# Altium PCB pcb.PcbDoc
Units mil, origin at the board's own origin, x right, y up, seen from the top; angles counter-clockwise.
Board outline 2805 x 2505 mil, 2 copper layers (Top Layer, Bottom Layer); 6 components, 40 nets, 144 pads, 0 vias.
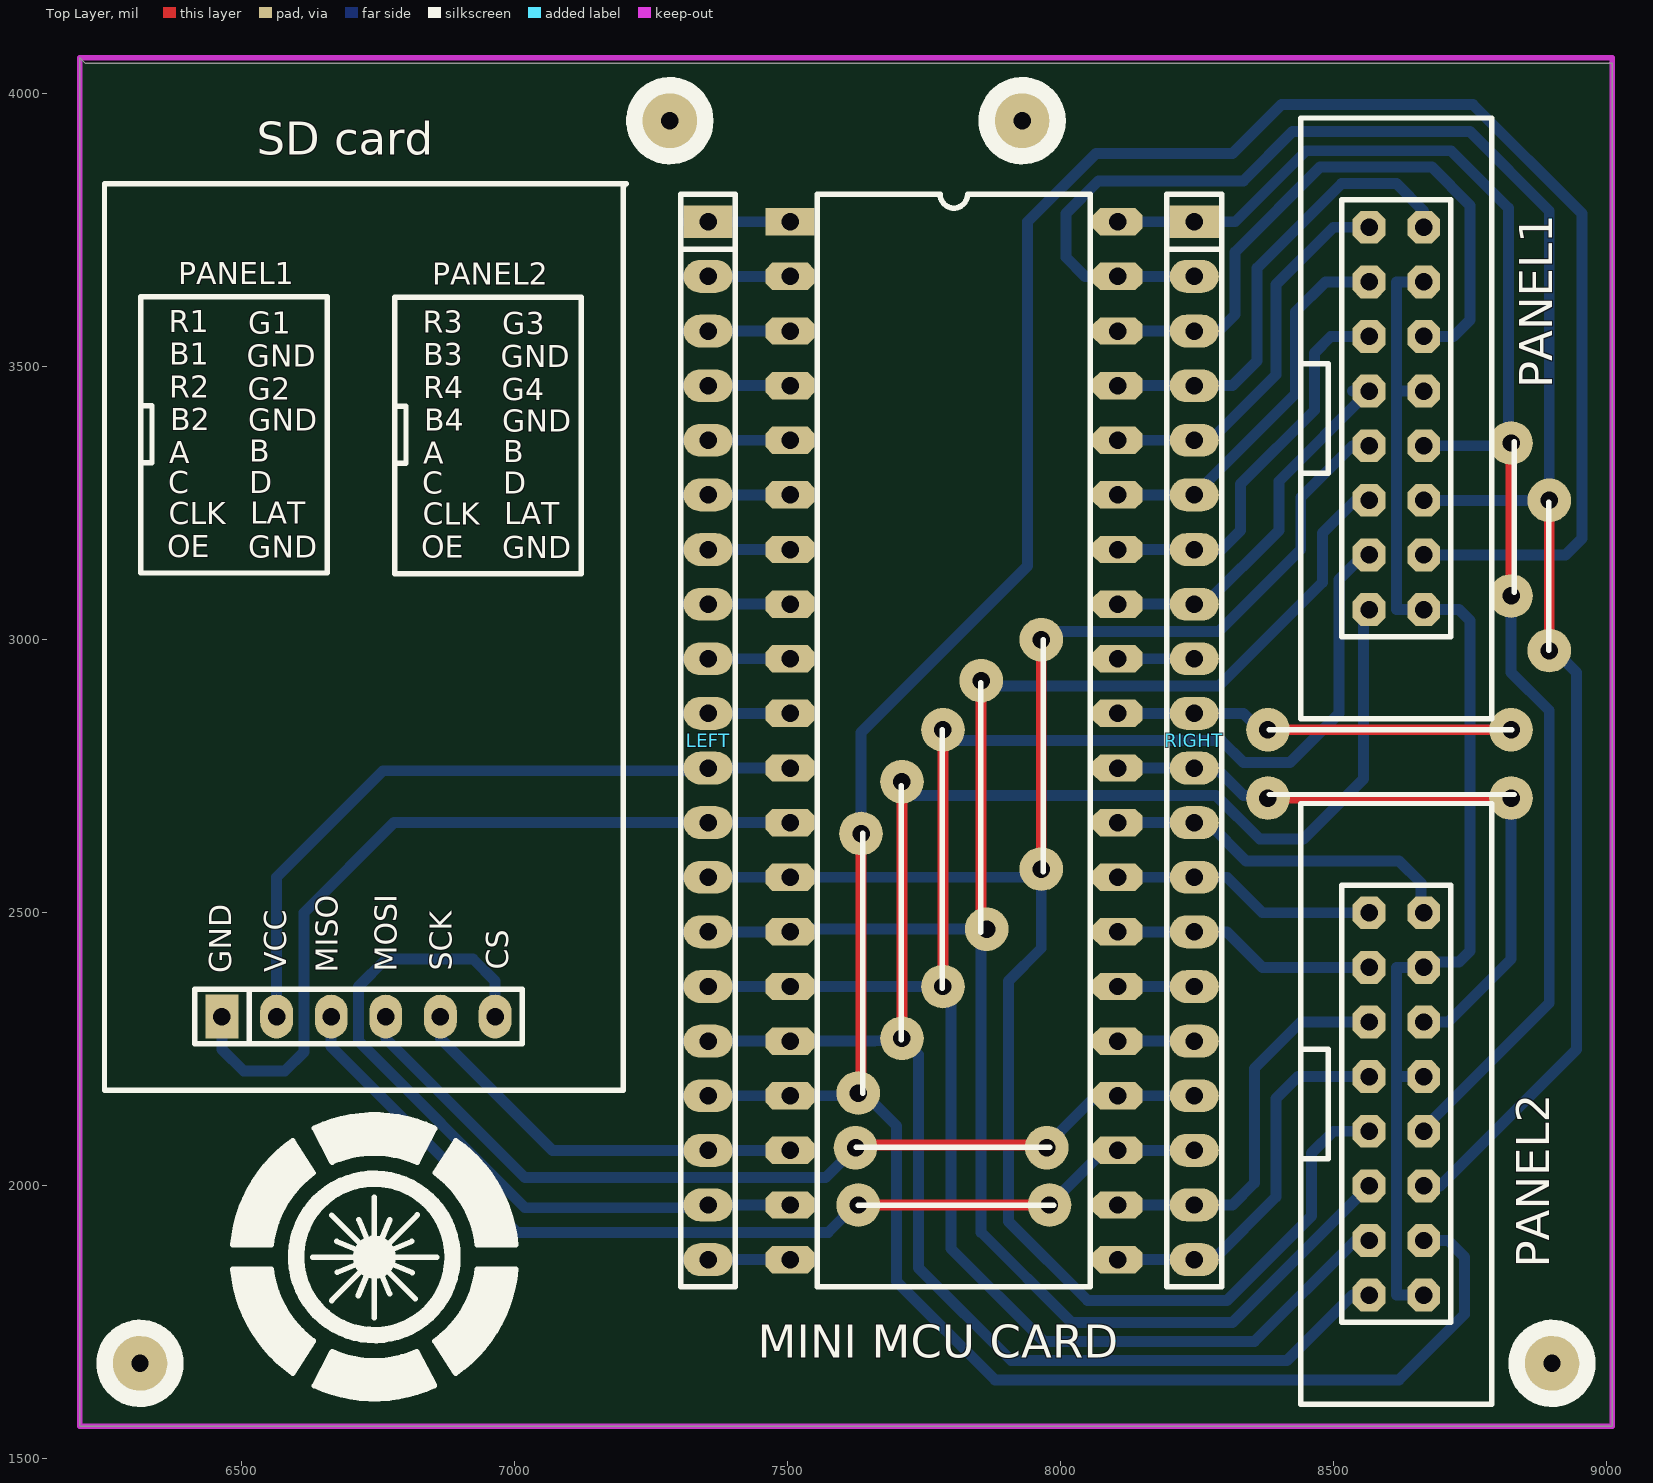
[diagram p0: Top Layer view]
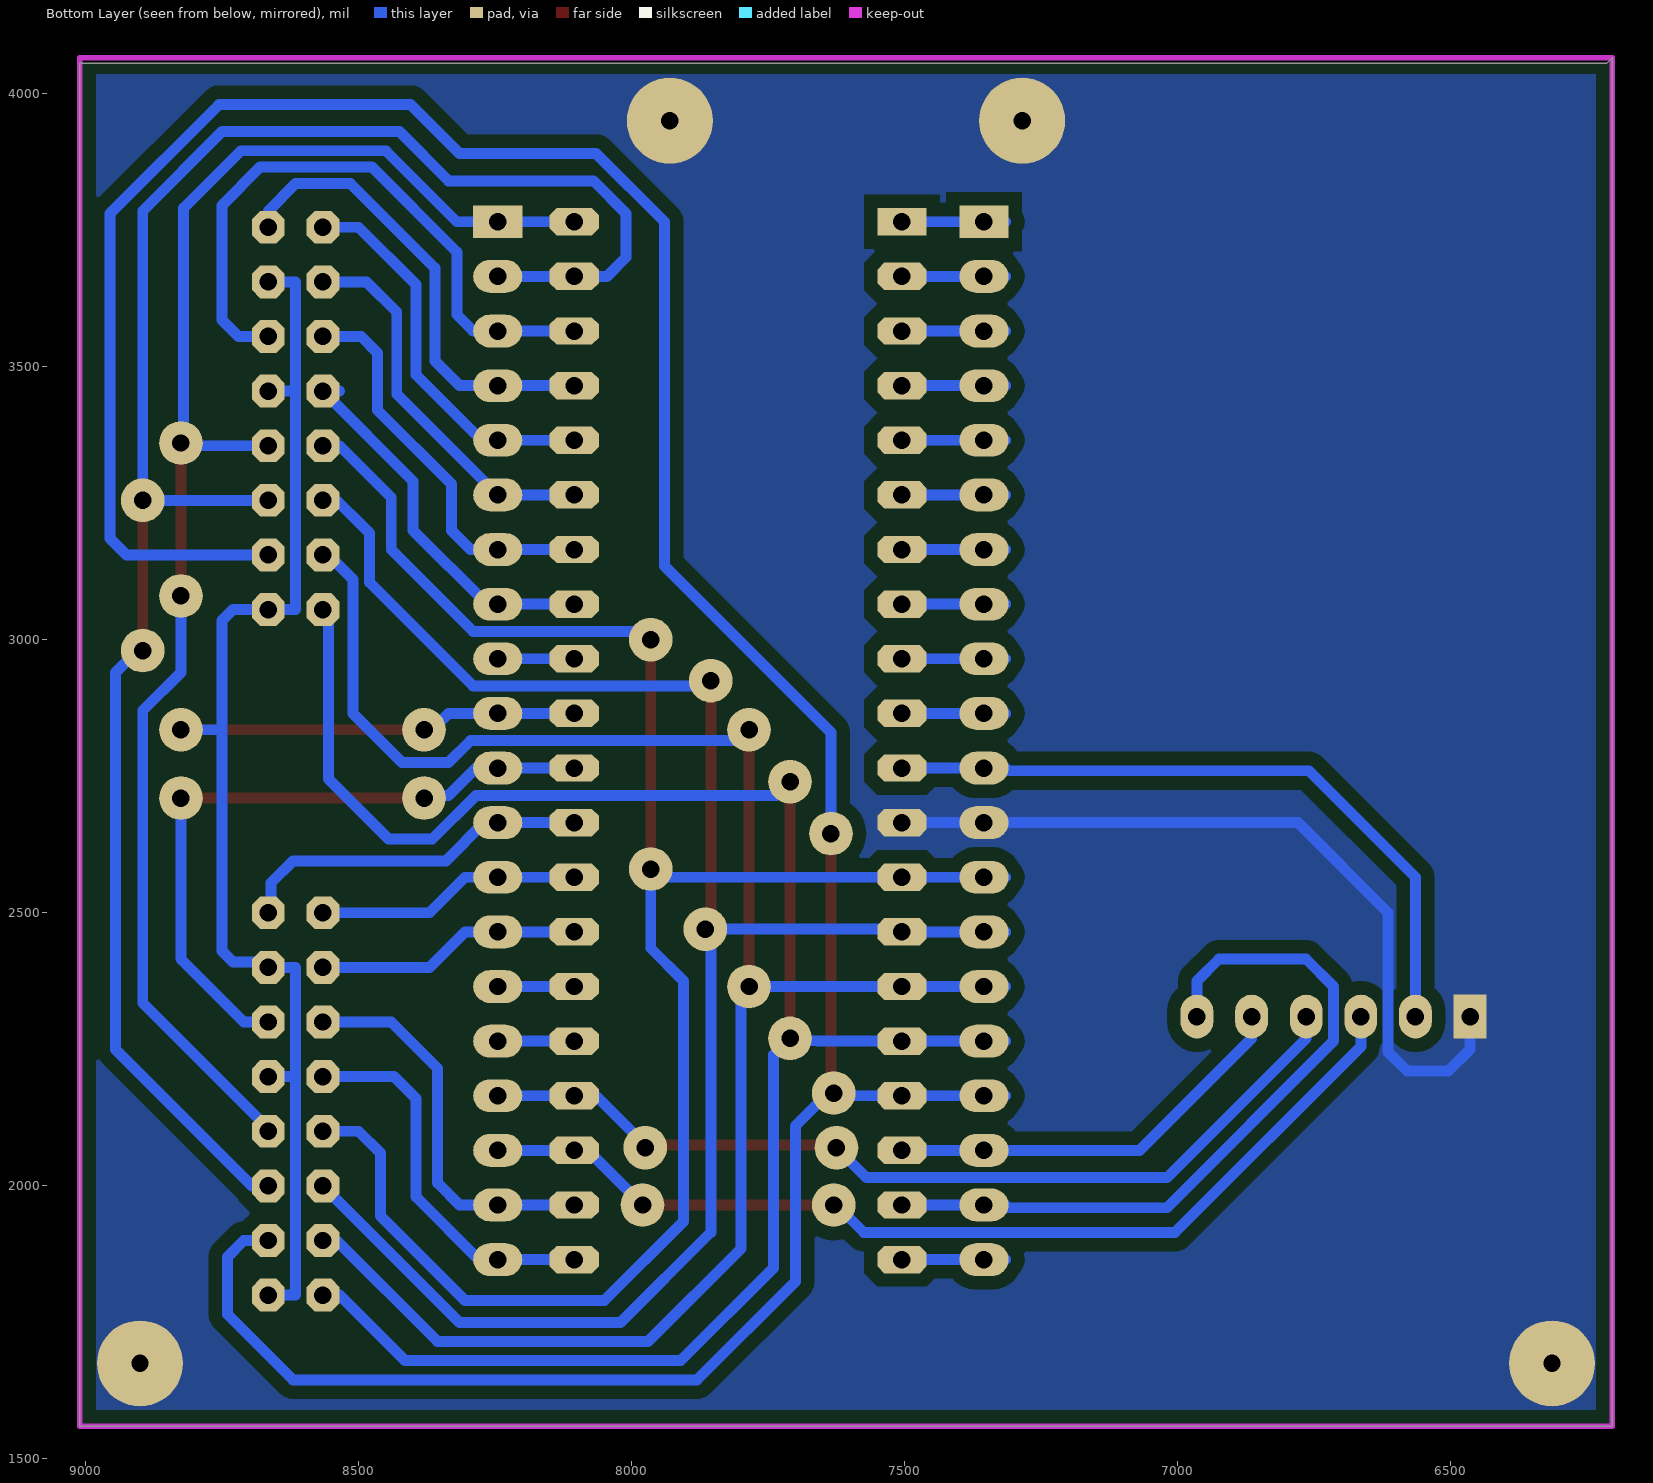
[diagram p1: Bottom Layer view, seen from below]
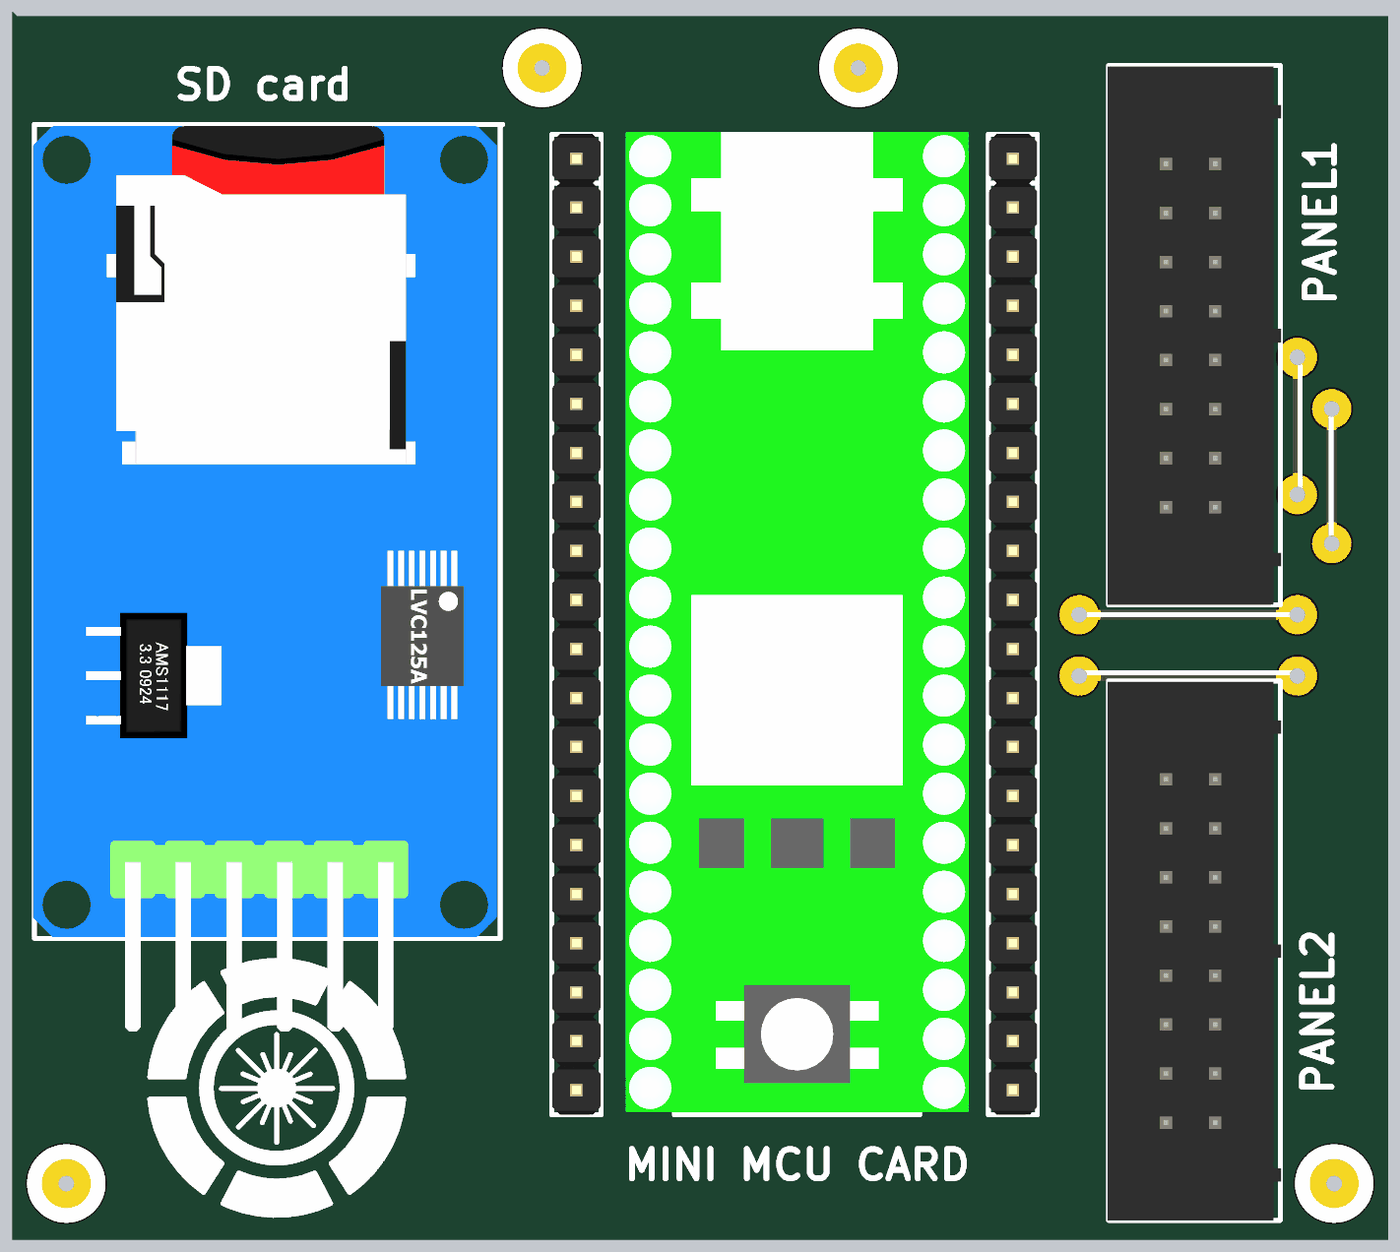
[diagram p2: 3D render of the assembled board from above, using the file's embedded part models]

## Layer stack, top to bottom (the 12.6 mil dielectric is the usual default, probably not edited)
Top Layer: signal copper 1.4
Dielectric: dielectric 12.6, FR-4, Dk 4.8
Bottom Layer: signal copper 1.4

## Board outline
6205,4065 6215,4055 9010,4055 9010,1560 6205,1560

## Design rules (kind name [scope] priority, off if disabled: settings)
Clearance [All] p1: gap=10
PolygonConnect [All] p1: connectstyle=Direct reliefconductorwidth=10 reliefentries=4 polygonreliefangle="90 Angle" airgapwidth=10
RoutingVias [All] p1: holewidth=28 width=50 viastyle="Through Hole" minholewidth=28 minwidth=50 maxholewidth=28 maxwidth=50
SolderMaskExpansion [All] p1: expansion=4
Width [All] p1: maxlimit=30 minlimit=10 preferedwidth=10 minimp=50.000000 maximp=50.000000 favimp=50.000000
28 further rules are at their usual default settings.

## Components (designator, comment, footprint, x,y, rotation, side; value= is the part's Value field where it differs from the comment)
LEFT "HDR-20" HDR-20 7355,3765 r270 top
"MINI MCU CARD" "MINI-GENERIC" "MINI - GENERIC" 7505,3765 r0 top (schematic designator PIC32)
PANEL1 "PANEL_CON" HDR-8x2 8640,3555 r270 top
PANEL2 "PANEL_CON" HDR-8x2 8640,2300 r270 top
RIGHT "HDR-20" HDR-20 8245,3765 r270 top
"SD card" "microSD" microSD 6465,2310 r0 top

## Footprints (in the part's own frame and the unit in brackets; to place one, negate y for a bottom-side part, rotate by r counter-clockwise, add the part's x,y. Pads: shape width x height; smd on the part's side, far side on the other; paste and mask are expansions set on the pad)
HDR-8x2 [mil]
  oct 60x60 hole 32: 1(-200,-75) 2(-100,-75) 3(0,-75) 4(100,-75) 5(200,-75) 6(300,-75) 7(400,-75) 8(500,-75) 9(500,25) 10(400,25) 11(300,25) 12(200,25) 13(100,25) 14(0,25) 15(-100,25) 16(-200,25)
  silkscreen extent -400,-200 700,150, body extent -398,-202 700,152, height 350
HDR-20 [mil]
  rect 60x90 hole 32: 1(0,0)
  oval 60x90 hole 32: 2(100,0) 3(200,0) 4(300,0) 5(400,0) 6(500,0) 7(600,0) 8(700,0) 9(800,0) 10(900,0) 11(1000,0) 12(1100,0) 13(1200,0) 14(1300,0) 15(1400,0) 16(1500,0) 17(1600,0) 18(1700,0) 19(1800,0) 20(1900,0)
  silkscreen extent -50,-50 1950,50, body extent -50,-49 1950,49, height 415
microSD [mil]
  rect 60x80 hole 32: 1(0,0)
  oval 60x80 hole 32: 2(100,0) 3(200,0) 4(300,0) 5(400,0) 6(500,0)
  silkscreen extent -215,-135 740,1525, body extent -217,-325 727,1521, height 636
"MINI - GENERIC" [mil]
  rect 90x50 hole 32: 1(0,0)
  oct 90x50 hole 32: 2(0,-100) 3(0,-200) 4(0,-300) 5(0,-400) 6(0,-500) 7(0,-600) 8(0,-700) 9(0,-800) 10(0,-900) 11(0,-1000) 12(0,-1100) 13(0,-1200) 14(0,-1300) 15(0,-1400) 16(0,-1500) 17(0,-1600) 18(0,-1700) 19(0,-1800) 20(0,-1900) 21(600,-1900) 22(600,-1800) 23(600,-1700) 24(600,-1600) 25(600,-1500) 26(600,-1400) 27(600,-1300) 28(600,-1200) 29(600,-1100) 30(600,-1000) 31(600,-900) 32(600,-800) 33(600,-700) 34(600,-600) 35(600,-500) 36(600,-400) 37(600,-300) 38(600,-200) 39(600,-100) 40(600,0)
  silkscreen extent 50,-1950 550,50, body extent -50,-1945 650,55, height 567

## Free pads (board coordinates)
  round 157.48 hole 32: 0(6315,1675) 0(7285,3950) 0(8900,1675) 1(7930,3950)
  round 80 hole 32: 2(7625,2070) 2(7630,1965) 2(7630,2170) 2(7635,2645) 2(7710,2270) 2(7710,2740) 2(7785,2365) 2(7785,2835) 2(7855,2925) 2(7865,2470) 2(7965,2580) 2(7965,3000) 2(7975,2070) 2(7980,1965) 2(8380,2710) 2(8380,2835) 2(8825,2710) 2(8825,2835) 2(8825,3080) 2(8825,3360) 2(8895,2980) 2(8895,3255)

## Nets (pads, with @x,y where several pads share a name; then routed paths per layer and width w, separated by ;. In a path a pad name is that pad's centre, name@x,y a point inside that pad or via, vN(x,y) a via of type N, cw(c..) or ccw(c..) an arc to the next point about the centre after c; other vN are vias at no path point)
GND: "MINI MCU CARD.31" pad.2@8380,2835 pad.2@8825,2835 PANEL1.9 PANEL1.13 PANEL1.15 PANEL2.9 PANEL2.13 PANEL2.15 RIGHT.10 | length 3094.8
  Top Layer w20: pad.2@8385,2835 8380,2835 pad.2@8825,2835
  Bottom Layer w20: 8105,2865 RIGHT.10 8335,2865 pad.2@8375,2825 ; 8615,2200 PANEL2.13@8660,2200 ; 8617.5,3455 PANEL1.13 ; PANEL2.9@8660,1800 8615,1800 8615,2400 8660,2400 8670,2410 8730,2410 8750,2430 8750,2835 ; PANEL1.15 8615,3655 8615,3055 PANEL1.9 8730,3055 8750,3035 8750,2835 ; pad.2@8825,2835 8750,2835
GND1: "MINI MCU CARD.12" "SD card.1" LEFT.12 pad.0 pad.1 | length 1454.4
  Bottom Layer w20: 6465,2310 6465,2250 6505,2210 6580,2210 6615,2245 6615,2500 6780,2665 LEFT.12 7505,2665
NetLEFT_1: "MINI MCU CARD.1" LEFT.1 | length 190
  Bottom Layer w20: LEFT.1@7315,3765 7505,3765
NetLEFT_2: "MINI MCU CARD.2" LEFT.2 | length 190
  Bottom Layer w20: LEFT.2@7315,3665 7505,3665
NetLEFT_3: "MINI MCU CARD.3" LEFT.3 | length 190
  Bottom Layer w20: LEFT.3@7315,3565 7505,3565
NetLEFT_4: "MINI MCU CARD.4" LEFT.4 | length 190
  Bottom Layer w20: LEFT.4@7315,3465 7505,3465
NetLEFT_5: "MINI MCU CARD.5" LEFT.5 | length 190
  Bottom Layer w20: LEFT.5@7315,3365 7505,3365
NetLEFT_6: "MINI MCU CARD.6" LEFT.6 | length 190
  Bottom Layer w20: LEFT.6@7315,3265 7505,3265
NetLEFT_7: "MINI MCU CARD.7" LEFT.7 | length 190
  Bottom Layer w20: LEFT.7@7315,3165 7505,3165
NetLEFT_8: "MINI MCU CARD.8" LEFT.8 | length 190
  Bottom Layer w20: LEFT.8@7315,3065 7505,3065
NetLEFT_9: "MINI MCU CARD.9" LEFT.9 | length 190
  Bottom Layer w20: LEFT.9@7315,2965 7505,2965
NetLEFT_10: "MINI MCU CARD.10" LEFT.10 | length 190
  Bottom Layer w20: LEFT.10@7315,2865 7505,2865
NetLEFT_13: "MINI MCU CARD.13" LEFT.13 pad.2@7965,2580 pad.2@7965,3000 PANEL1.5 PANEL2.5 | length 3458.4
  Top Layer w20: pad.2@7965,2580 pad.2@7965,3000
  Bottom Layer w20: LEFT.13@7315,2565 7505,2565 pad.2@7965,2565 ; pad.2@7965,2580 pad.2@7965,2565 ; pad.2@7965,3000 7980,3015 8290,3015 8440,3165 8440,3260 8535,3355 PANEL1.5 ; PANEL2.5 8500,2100 8460,2060 8460,1945 8305,1790 8050,1790 7905,1935 7905,2375 7965,2435 pad.2@7965,2565
NetLEFT_14: "MINI MCU CARD.14" LEFT.14 pad.2@7855,2925 pad.2@7865,2470 PANEL1.6 PANEL2.6 | length 3373.8
  Top Layer w20: pad.2@7855,2925 7855,2480 pad.2@7865,2470
  Bottom Layer w20: LEFT.14@7315,2465 7505,2465 ; 7510,2470 7865,2470 7855,2460 7855,1915 8020,1750 8315,1750 PANEL2.6 ; pad.2@7855,2925 7875,2915 8290,2915 8480,3105 8480,3195 PANEL1.6@8552.5,3267.5 ; PANEL1.6@8545,3255 PANEL1.6 ; PANEL2.6@8550,2000 PANEL2.6@8560,2000
NetLEFT_15: "MINI MCU CARD.15" LEFT.15 pad.2@7785,2365 pad.2@7785,2835 PANEL1.7 PANEL2.7 | length 3439
  Top Layer w20: pad.2@7785,2365 pad.2@7785,2835
  Bottom Layer w20: LEFT.15@7315,2365 7505,2365 7785,2365 7800,2350 7800,1885 7970,1715 8355,1715 8540,1900 PANEL2.7@8560,1900 ; pad.2@7785,2835 7805,2815 8295,2815 8335,2775 8420,2775 8510,2865 8510,3110 8555,3155 PANEL1.7
NetLEFT_16: "MINI MCU CARD.16" LEFT.16 pad.2@7710,2270 pad.2@7710,2740 PANEL1.8 PANEL2.8 | length 3450.6
  Top Layer w20: pad.2@7710,2270 pad.2@7710,2740
  Bottom Layer w20: LEFT.16@7315,2265 7505,2265 7660,2265 7710,2270 7740,2240 7740,1850 7910,1680 8415,1680 8535,1800 PANEL2.8@8560,1800 ; pad.2@7735,2715 8285,2715 8365,2635 8445,2635 8555,2745 8555,3045 PANEL1.8
NetLEFT_17: "MINI MCU CARD.17" LEFT.17 pad.2@7630,2170 pad.2@7635,2645 PANEL1.10 PANEL2.10 | length 5861.3
  Top Layer w20: pad.2@7635,2175 pad.2@7635,2645
  Bottom Layer w20: LEFT.17@7315,2165 7505,2165 7625,2165 pad.2@7630,2170 ; pad.2@7630,2175 7635,2175 7700,2110 7700,1825 7880,1645 8620,1645 8740,1765 8740,1870 8710,1900 PANEL2.10@8660,1900 ; pad.2@7635,2645 7635,2830 7940,3135 7940,3765 8065,3890 8315,3890 8405,3980 8755,3980 8955,3780 8955,3185 8925,3155 PANEL1.10
NetLEFT_18: "MINI MCU CARD.18" "SD card.5" LEFT.18 | length 804.9
  Bottom Layer w20: 6865,2310 6865,2270 7070,2065 LEFT.18 ; LEFT.18@7315,2065 7505,2065
NetLEFT_19: "MINI MCU CARD.19" "SD card.6" LEFT.19 | length 1403.6
  Bottom Layer w20: 6965,2310 6965,2375 6925,2415 6765,2415 6715,2365 6715,2265 7020,1960 LEFT.19@7350,1960 ; LEFT.19@7315,1965 7505,1965
NetLEFT_20: "MINI MCU CARD.20" LEFT.20 | length 190
  Bottom Layer w20: LEFT.20@7315,1865 7505,1865
"NetMINI MCU CARD_21": "MINI MCU CARD.21" PANEL2.4 RIGHT.20 | length 699.2
  Bottom Layer w20: 8105,1865 RIGHT.20 8280,1865 8395,1980 8395,2160 8435,2200 PANEL2.4@8560,2200
"NetMINI MCU CARD_22": "MINI MCU CARD.22" PANEL2.3 RIGHT.19 | length 721.8
  Bottom Layer w20: 8105,1965 RIGHT.19 8315,1965 8355,2005 8355,2215 8440,2300 PANEL2.3
"NetMINI MCU CARD_23": "MINI MCU CARD.23" "SD card.3" pad.2@7630,1965 pad.2@7980,1965 RIGHT.18 | length 1833
  Top Layer w20: pad.2@7625,1965 pad.2@7975,1965
  Bottom Layer w20: 6665,2310 6665,2255 7005,1915 7575,1915 pad.2@7625,1965 ; pad.2@7980,1965 8080,2065 8105,2065 RIGHT.18
"NetMINI MCU CARD_24": "MINI MCU CARD.24" "SD card.4" pad.2@7625,2070 pad.2@7975,2070 RIGHT.17 | length 1697.8
  Top Layer w20: pad.2@7625,2070 7630,2075 pad.2@7970,2075
  Bottom Layer w20: 6765,2310 6765,2270 7020,2015 7570,2015 7625,2070 pad.2@7610,2070 ; pad.2@7975,2075 8065,2165 8105,2165 RIGHT.17
"NetMINI MCU CARD_25": "MINI MCU CARD.25" RIGHT.16 | length 140
  Bottom Layer w20: 8105,2265 RIGHT.16
"NetMINI MCU CARD_26": "MINI MCU CARD.26" RIGHT.15 | length 140
  Bottom Layer w20: 8105,2365 RIGHT.15
"NetMINI MCU CARD_27": "MINI MCU CARD.27" PANEL2.2 RIGHT.14 | length 441.9
  Bottom Layer w20: 8105,2465 RIGHT.14 ; RIGHT.14@8285,2465 8305,2465 8370,2400 PANEL2.2@8560,2400
"NetMINI MCU CARD_28": "MINI MCU CARD.28" PANEL2.1 RIGHT.13 | length 446.9
  Bottom Layer w20: 8105,2565 RIGHT.13 ; RIGHT.13@8280,2565 8305,2565 8370,2500 PANEL2.1@8560,2500
"NetMINI MCU CARD_29": "MINI MCU CARD.29" PANEL2.16 RIGHT.12 | length 655.6
  Bottom Layer w20: 8105,2665 RIGHT.12 8270,2665 8340,2595 8620,2595 8660,2555 PANEL2.16@8660,2500
"NetMINI MCU CARD_30": "MINI MCU CARD.30" pad.2@8380,2710 pad.2@8825,2710 PANEL2.14 RIGHT.11 | length 1217.5
  Top Layer w20: pad.2@8380,2710 pad.2@8825,2710
  Bottom Layer w20: 8105,2765 RIGHT.11 ; RIGHT.11@8285,2765 8335,2715 pad.2@8390,2715 ; PANEL2.14@8660,2300 8710,2300 8825,2415 8825,2695 pad.2@8815,2705
"NetMINI MCU CARD_33": "MINI MCU CARD.33" PANEL1.4 RIGHT.8 | length 704.3
  Bottom Layer w20: 8105,3065 RIGHT.8 8265,3065 8400,3200 8400,3290 PANEL1.4 PANEL1.4@8535,3455
"NetMINI MCU CARD_34": "MINI MCU CARD.34" PANEL1.3 RIGHT.7 | length 747.8
  Bottom Layer w20: 8105,3165 RIGHT.7 8295,3165 8330,3200 8330,3285 8465,3420 8465,3525 8495,3555 PANEL1.3 PANEL1.3@8550,3555
"NetMINI MCU CARD_35": "MINI MCU CARD.35" PANEL1.2 RIGHT.6 | length 739.4
  Bottom Layer w20: 8105,3265 RIGHT.6 8430,3450 8430,3600 8485,3655 PANEL1.2 PANEL1.2@8535,3655
"NetMINI MCU CARD_36": "MINI MCU CARD.36" PANEL1.1 RIGHT.5 | length 718.2
  Bottom Layer w20: 8105,3365 RIGHT.5 8275,3365 8395,3485 8395,3650 8500,3755 PANEL1.1
"NetMINI MCU CARD_37": "MINI MCU CARD.37" PANEL1.16 RIGHT.4 | length 863.6
  Bottom Layer w20: 8105,3465 RIGHT.4 8315,3465 8360,3510 8360,3680 8515,3835 8615,3835 8665,3785 PANEL1.16
"NetMINI MCU CARD_38": "MINI MCU CARD.38" PANEL1.14 RIGHT.3 | length 1173.1
  Bottom Layer w20: 8105,3565 RIGHT.3 8290,3565 8320,3595 8320,3710 8475,3865 8680,3865 8750,3795 8750,3585 8720,3555 PANEL1.14
"NetMINI MCU CARD_39": "MINI MCU CARD.39" pad.2@8895,2980 pad.2@8895,3255 PANEL1.11 PANEL2.11 RIGHT.2 | length 3516.8
  Top Layer w20: pad.2@8895,2980 pad.2@8895,3255
  Bottom Layer w20: RIGHT.2 8105,3665 8045,3665 8010,3700 8010,3780 8070,3840 8335,3840 8425,3930 8750,3930 8895,3785 8895,3255 PANEL1.11 ; PANEL2.11@8660,2000 8695,2000 8945,2250 8945,2940 8905,2980 pad.2@8895,2980
"NetMINI MCU CARD_40": "MINI MCU CARD.40" pad.2@8825,3080 pad.2@8825,3360 PANEL1.12 PANEL2.12 RIGHT.1 | length 2788.7
  Top Layer w20: pad.2@8825,3080 pad.2@8825,3360
  Bottom Layer w20: 8105,3765 RIGHT.1 8320,3765 8450,3895 8715,3895 8820,3790 8820,3355 PANEL1.12 ; PANEL2.12@8660,2100 8895,2335 8895,2870 8825,2940 pad.2@8825,3080
VCC: "MINI MCU CARD.32" RIGHT.9 | length 140
  Bottom Layer w20: 8105,2965 RIGHT.9
VCC1: "MINI MCU CARD.11" "SD card.2" LEFT.11 | length 1335.8
  Bottom Layer w20: 6565,2295 6565,2565 6760,2760 LEFT.11@7360,2760 ; LEFT.11@7315,2765 7505,2765

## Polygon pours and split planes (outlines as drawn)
GND1 on Bottom Layer "GND1" (solid, remove dead copper, pour order 4): 6205,4055 9010,4055 9005,4050 9005,1570 9005,1565 9010,1560 6205,1560
GND1 on Bottom Layer "GND1" (solid, remove dead copper, pour order 2): 6205,4065 9010,4065 9010,1560 6205,1560

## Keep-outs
Keep-Out Layer:
  lines w10: 6205,1560 9010,1560 9010,4065 6205,4065 6205,1560

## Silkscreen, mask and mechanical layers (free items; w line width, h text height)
Top Overlay:
  circle w30: c6315,1675 r65
  circle w30: c8900,1675 r65
  circle w30: c7930,3950 r65
  circle w30: c7285,3950 r65
  circle w10: c6744,1869.5 r34.56
  circle w20: c6744,1869.5 r23.01
  circle w30: c6744,1870 r143.21
  region: 6594.87,1657.02 6609,1676 6632.59,1716.09 6589,1759.68 6564,1804 6551.66,1847.34 6484.99,1847.34 6493,1805 6507,1764 6532,1722 6561,1682 6561,1681
  region: 6821.51,1696.54 6840.53,1660 6853.88,1634.36 6805,1616 6747,1610 6687,1618 6634.54,1634.36 6654,1671 6666.39,1695.76 6702,1685 6741,1680 6781,1684
  region: 6932.7,1847.34 7003.01,1847.34 6997,1805 6987,1771 6970,1733.89 6933,1692 6893.13,1657.02 6867,1696.98 6855.01,1719.01 6884,1744 6911,1775
  region: 6855.87,2023.98 6865.44,2039 6893.11,2082.44 6950,2032 6985,1969 6998,1930 7002,1892.34 6932.7,1892.34 6924,1929 6894,1987
  region: 6666.49,2043.46 6653,2073 6634.12,2105.64 6687,2123 6757.87,2132.61 6853.88,2110.04 6841,2076 6822.29,2043.12 6806,2050 6751,2059 6691,2055
  region: 6484.99,1892.34 6484.99,1910.99 6514,1996 6559,2054 6594.87,2082.02 6606,2060 6632.11,2023.56 6594,1984 6566,1937 6553,1892.34
  lines w10: 6317,3324 6337,3324 6337,3428 6324,3428 ; 6484.99,1892.34 6555.27,1892.34 ; 6484.99,1892.66 cw(c6744,1870) 6594.87,2082.98 ; 6551.66,1847.34 6484.99,1847.34 ccw(c6744,1870) 6594.87,1657.02 6632.11,1715.44 ; 6555.31,1847.77 ccw(c6744,1870) 6632.59,1716.09 ; 6555.32,1892.33 cw(c6744,1870) 6632.14,2023.58 ; 6594.87,2082.02 6632.11,2023.56 ; 6631,1869 6858,1869 ; 6634.12,1634.36 ccw(c6744,1870) 6853.88,1634.36 6821.51,1696.54 cw(c6744,1870) 6666.69,1696.44 ; 6634.3,1634.12 6666.39,1695.76 ; 6665.59,1946.59 6819.09,1793.09 ; 6665.91,1790.09 6822.91,1947.09 ; 6666.49,2043.46 6634.12,2105.64 cw(c6744,1870) 6853.88,2105.64 ; 6666.57,2043.51 cw(c6744,1870) 6822.29,2043.12 6854.39,2104.76 ; 6675.16,1898.38 6813.1,1841.24 ; 6675.76,1841.59 6812.49,1898.23 ; 6714.62,1799.16 6772.26,1938.31 ; 6715.74,1938.31 6772.11,1802.22 ; 6744,1759 6744,1979 ; 6782,3323 6802,3323 6802,3427 6789,3427 ; 6855.68,2023.71 cw(c6744,1870) 6932.7,1892.19 ; 6855.87,2023.98 6893.11,2082.44 ; 6892.11,1657.56 6855.01,1715.8 ccw(c6744,1870) 6932.64,1847.35 ; 6893.13,1657.02 ccw(c6744,1870) 7003.01,1847.34 6932.7,1847.34 ; 6893.13,2082.98 cw(c6744,1870) 7003.01,1892.66 ; 6932.7,1892.34 7003.01,1892.34 ; 7625.98,2070.87 7980.31,2070.87 ; 7629.92,1964.57 7988.19,1964.57 ; 7637.8,2169.29 7637.8,2645.67 ; 7708.66,2267.72 7708.66,2732.28 ; 7783.46,2362.2 7783.46,2834.65 ; 7854.33,2464.57 7854.33,2921.26 ; 7968.5,2574.8 7968.5,3000 ; 8381.89,2716.54 8830.71,2716.54 ; 8381.89,2834.65 8826.77,2834.65 ; 8830.71,3086.61 8830.71,3362.2 ; 8893.7,2980.32 8893.7,3251.97 ; 6316,3122 6658,3122 6658,3628 6316,3628 6316,3122 ; 6781,3121 6781,3627 7123,3627 7123,3121 6781,3121
  text "PANEL1" at 6385,3651 h40
  text "PANEL2" at 6850,3650 h40
  text "R1" at 6368,3563 h40
  text "R3" at 6833,3562 h40
  text "G1" at 6513,3560 h40
  text "G3" at 6978,3559 h40
  text "B1" at 6369,3503 h40
  text "B3" at 6834,3502 h40
  text "GND" at 6510,3500 h40
  text "GND" at 6975,3499 h40
  text "R2" at 6369,3443 h40
  text "R4" at 6834,3442 h40
  text "G2" at 6512,3439 h40
  text "G4" at 6977,3438 h40
  text "B2" at 6370,3383 h40
  text "GND" at 6513,3382 h40
  text "B4" at 6835,3382 h40
  text "GND" at 6978,3381 h40
  text "B" at 6515,3326 h40
  text "B" at 6980,3325 h40
  text "A" at 6369,3323 h40
  text "A" at 6834,3322 h40
  text "C" at 6367,3268 h40
  text "D" at 6515,3268 h40
  text "C" at 6832,3267 h40
  text "D" at 6980,3267 h40
  text "LAT" at 6517,3212 h40
  text "CLK" at 6368,3211 h40
  text "LAT" at 6982,3211 h40
  text "CLK" at 6833,3210 h40
  text "OE" at 6365,3151 h40
  text "GND" at 6513,3150 h40
  text "OE" at 6830,3150 h40
  text "GND" at 6978,3149 h40
  text "CS" at 6989,2396 h40 r90
  text "SCK" at 6886,2394 h40 r90
  text "MOSI" at 6785,2392 h40 r90
  text "VCC" at 6583,2391 h40 r90
  text "MISO" at 6677,2390 h40 r90
  text "GND" at 6482,2389 h40 r90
